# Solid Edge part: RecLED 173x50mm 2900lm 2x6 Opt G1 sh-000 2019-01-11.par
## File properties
Author: lukasz.lemanski
Template: iso metric part.par
Last saved by: lukasz.lemanski
Revision: 1
Application: Solid Edge
Username: lukasz.lemanski
Gęstość: 0,000 kg/m^3
Dokładność: 0,990
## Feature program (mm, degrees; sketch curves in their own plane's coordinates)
body "unnamed Body 1"
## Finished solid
Body 1: solid body, 880 faces, 2269 edges, 1405 vertices.
  Faces by surface: plane 393, cylinder 329, spline 80, torus 35, cone 26, sphere 10, spun 7
  Edges by curve: line 1324, circle 505, curve on surface 282, ellipse 114, spline 38, intersection 6
Bounding box of the edges (mm; curved faces can reach further): 49.500 x 4.950 x 172.200, from (-24.75, -3.45, -86.1) to (24.75, 1.5, 86.1).
Cylindrical faces by radius (mm): R0.05 x48, R0.1 x144, R0.2 x51, R0.2002 x2, R0.2169 x3, R0.25 x12, R0.3 x2, R0.3373 x3, R0.4 x8, R0.4006 x2, R0.4008 x2, R0.525 x2, R0.6 x12, R1 x7, R1.05 x12, R1.0894 x2, R1.1 x14, R1.6 x3
Conical faces (half-angle, radius in mm at the cone's reference point): 0.5 deg R0.5056 x4, 0.5 deg R1.0082 x4, 1 deg R0.5511 x2, 10 deg R0.2132 x2, 10 deg R0.4132 x2, 18.4844 deg R1.0657 x4, 27.363 deg R0.6214 x2, 45 deg R0.575 x2, 45 deg R0.625 x4
Toroidal faces (ring radius, tube radius in mm): R-0.0731 r1.395 x12, R0.1 r0.2 x1, R0.8 r0.2 x4, R0.8522 r0.3 x2, R0.9002 r0.2 x1, R0.9018 r0.2 x1, R1.3 r0.2 x2, R1.4708 r0.15 x12
Spherical faces by radius (mm): R0.2 x8, R0.6 x2
Planar faces by outward normal: +x 61, +y 20, +z 57, -x 61, -y 32, -z 78, oblique 84
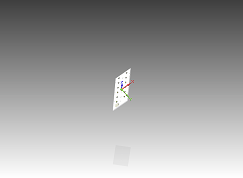
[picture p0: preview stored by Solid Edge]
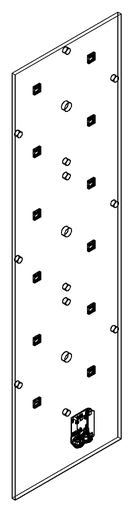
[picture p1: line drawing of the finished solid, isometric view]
